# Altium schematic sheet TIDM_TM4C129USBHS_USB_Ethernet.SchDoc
size 431 x 279 mm; Date: Not shown in title block; ApprovedBy: Not shown in title block; CheckedBy: Not shown in title block; Author: Not shown in title block; CompanyName: Not shown in title block; Engineer: Not shown in title block; Organization: Not shown in title block; Address1: Not shown in title block; Address2: Not shown in title block; Address3: Not shown in title block; Address4: Not shown in title block; DocumentNumber: 1; Revision: Use project parameter SCH_Rev; SheetNumber: 3; SheetTotal: 3; PageSetup: Record=PageOptions¦CenterHorizontal=True¦CenterVertical=True¦PrintScale=1.00¦XCorrection=1.00¦YCorrection=1.00¦PrintKind=0¦BorderSize=5000000¦LeftOffset=0¦BottomOffset=0¦Orientation=2¦PaperLength=1000¦PaperWidth=1000¦Scale=100¦PaperSource=15¦PrintQuality=600¦MediaType=1¦DitherType=10¦PaperKind=Letter¦PrintScaleMode=1
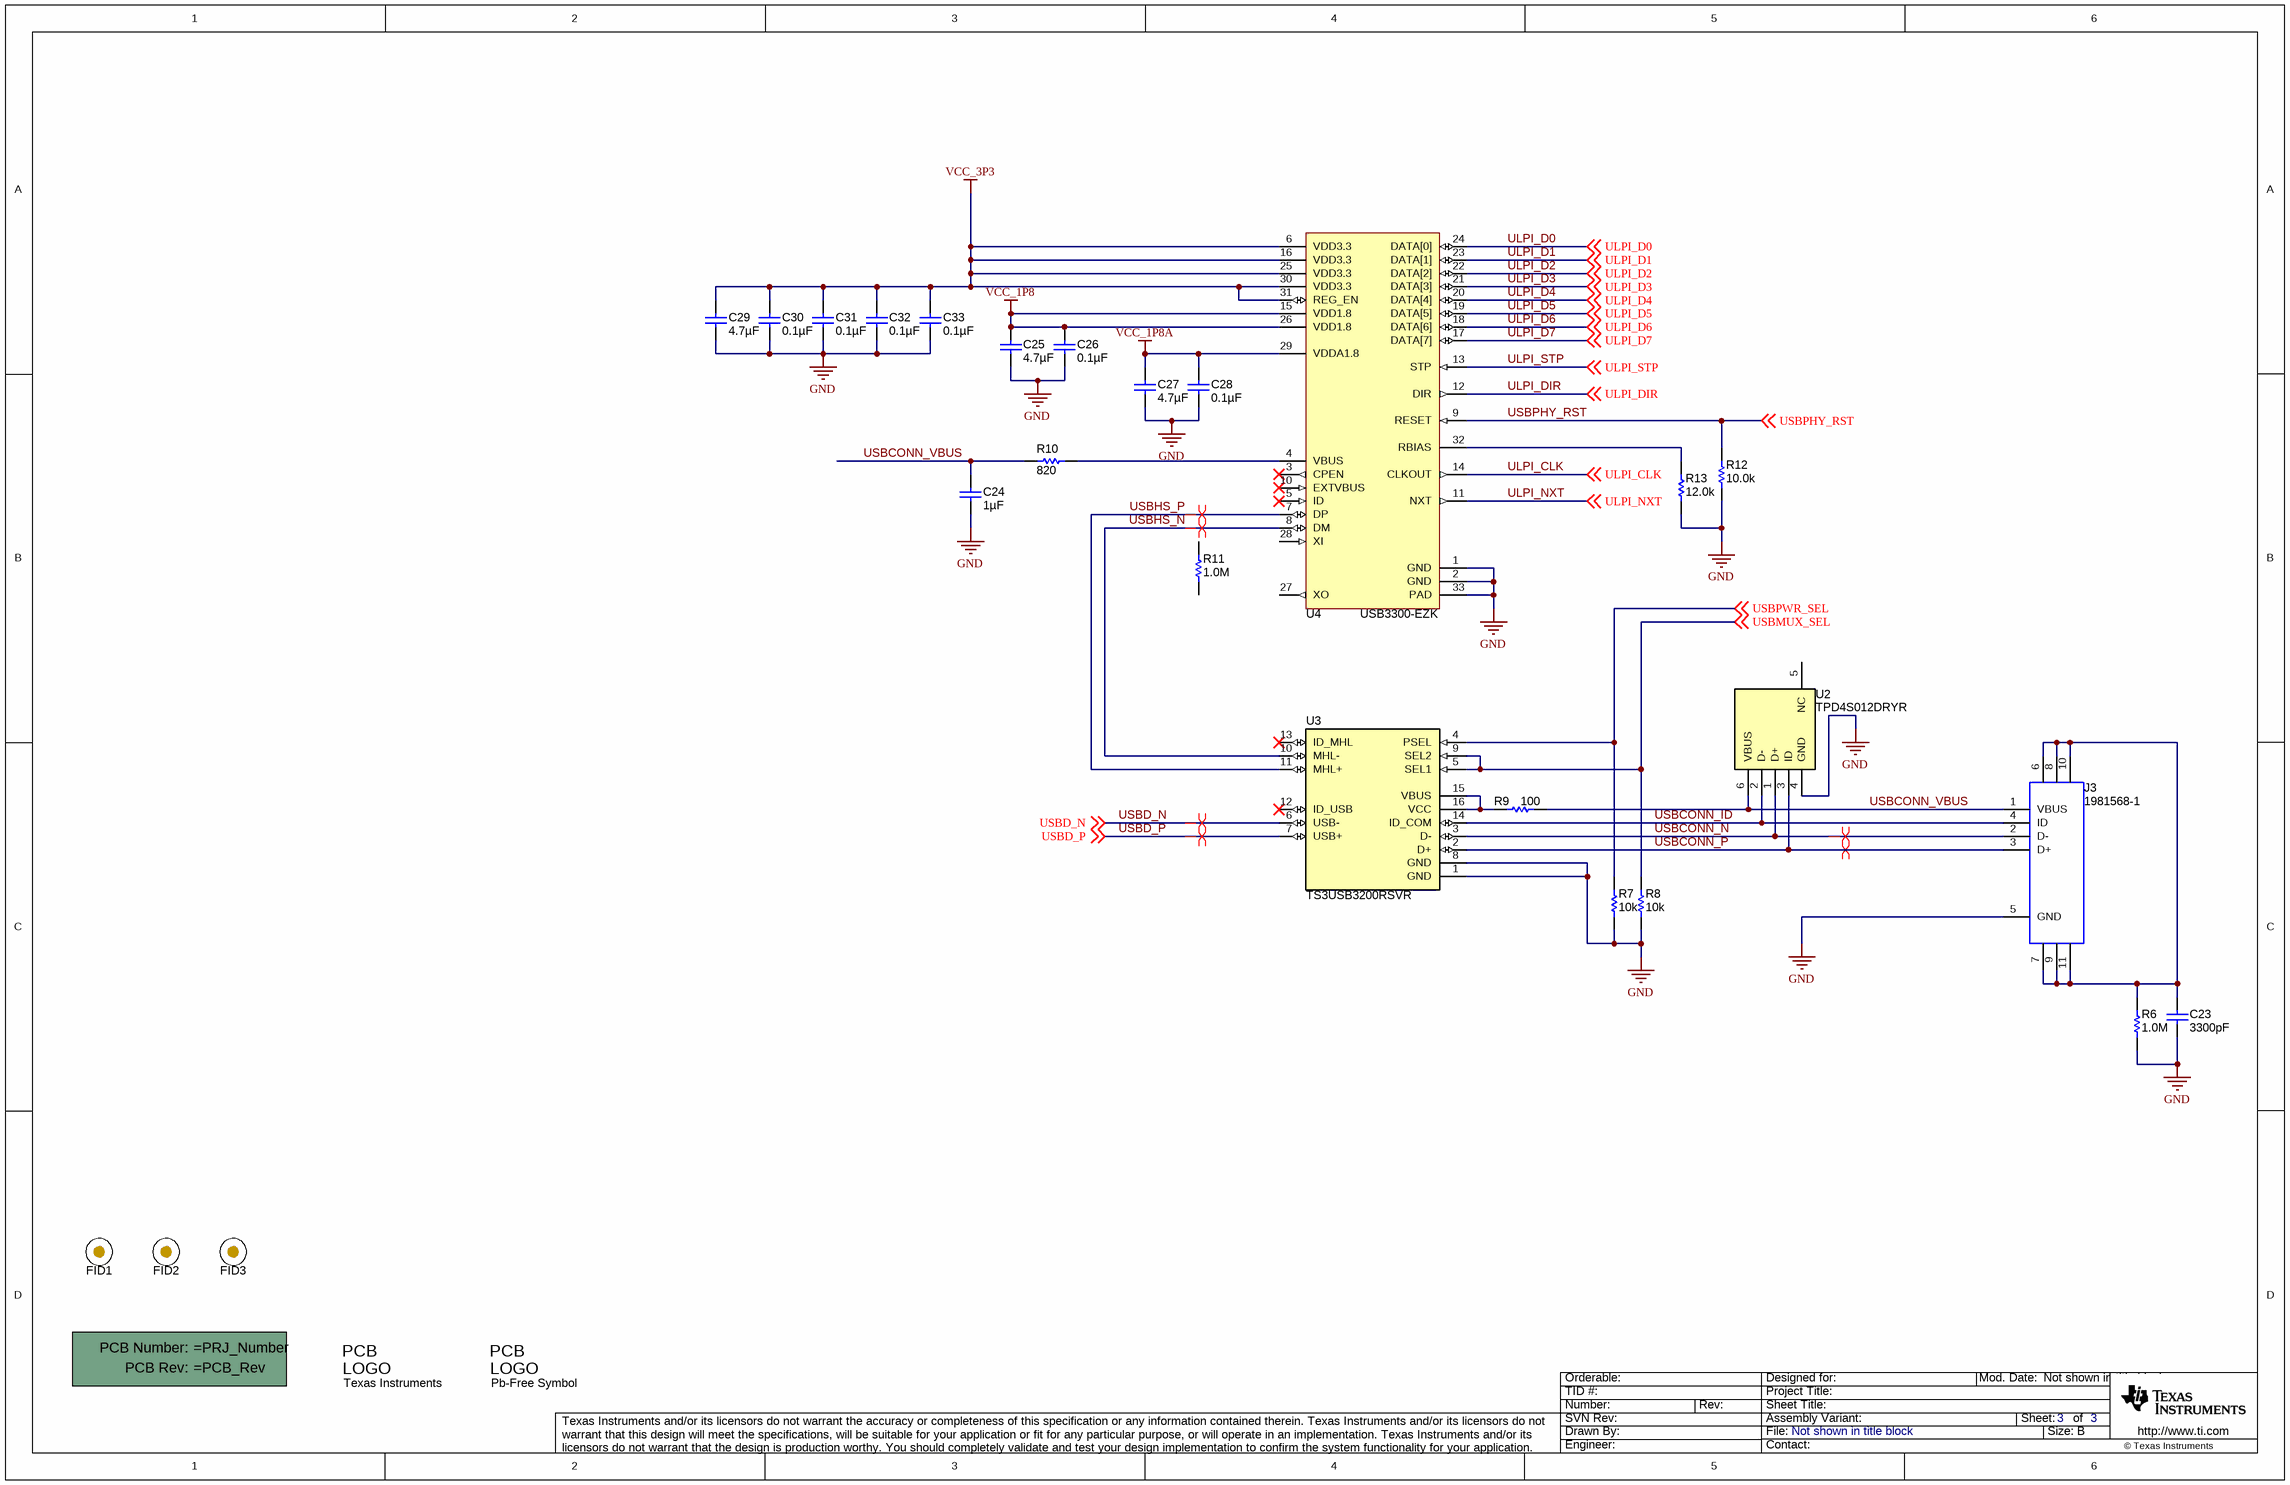
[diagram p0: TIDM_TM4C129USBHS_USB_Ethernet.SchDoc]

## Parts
!PCB  Printed Circuit Board  (value not drawn)  (mechanical)
C23  ValueDisplayed: 3300pF  [0603]  (hidden comment: C0603X332K5RACTU)
C24  ValueDisplayed: 1µF  [0603]  (hidden comment: GRM188R71A105KA61D)
C25  ValueDisplayed: 4.7µF  [0603]  (hidden comment: JMK107BB7475MA-T)
C26  ValueDisplayed: 0.1µF  [0603]  (hidden comment: 06035C104KAT2A)
C27  ValueDisplayed: 4.7µF  [0603]  (hidden comment: JMK107BB7475MA-T)
C28  ValueDisplayed: 0.1µF  [0603]  (hidden comment: 06035C104KAT2A)
C29  ValueDisplayed: 4.7µF  [0603]  (hidden comment: JMK107BB7475MA-T)
C30  ValueDisplayed: 0.1µF  [0603]  (hidden comment: 06035C104KAT2A)
C31  ValueDisplayed: 0.1µF  [0603]  (hidden comment: 06035C104KAT2A)
C32  ValueDisplayed: 0.1µF  [0603]  (hidden comment: 06035C104KAT2A)
C33  ValueDisplayed: 0.1µF  [0603]  (hidden comment: 06035C104KAT2A)
FID1  Fiducial  [Fiducial10-20]  (value not drawn)
FID2  Fiducial  [Fiducial10-20]  (value not drawn)
FID3  Fiducial  [Fiducial10-20]  (value not drawn)
J3  1981568-1  [TE_1981568-1]
Logo1  Texas Instruments  [TI_Stacked_Overlay_Small]  (no BOM)
Logo2  Pb-Free Symbol  [Pb-Free_Overlay_Small]  (no BOM)
R6  ValueDisplayed: 1.0M  [0603]  (hidden comment: CRCW06031M00JNEA)
R7  ValueDisplayed: 10k  [0603]  (hidden comment: RC0603JR-0710KL)
R8  ValueDisplayed: 10k  [0603]  (hidden comment: RC0603JR-0710KL)
R9  ValueDisplayed: 100  [0603]  (hidden comment: CRCW0603100RJNEA)
R10  ValueDisplayed: 820  [0603]  (hidden comment: RC0603FR-07820RL)
R11  ValueDisplayed: 1.0M  [0603]  (hidden comment: CRCW06031M00JNEA)
R12  ValueDisplayed: 10.0k  [0603]  (hidden comment: RCG060310K0FKEA)
R13  ValueDisplayed: 12.0k  [0603]  (hidden comment: RC0603FR-0712KL)
U2  TPD4S012DRYR  [DRY0006A]
U3  TS3USB3200RSVR  [RSV0016A]
U4  USB3300-EZK  [Microchip_32QFN-3304-5x5B]

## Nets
GND: C23.2 C24.2 C25.2 C26.2 C27.2 C28.2 C29.2 C30.2 C31.2 C32.2 C33.2 J3.5(GND) R6.1 R7.1 R8.1 R12.1 R13.1 U2.4(GND) U3.1(GND) U3.8(GND) U4.1(GND) U4.2(GND) U4.33(PAD)
VCC_1P8: C25.1 C26.1 U4.15(VDD1.8) U4.26(VDD1.8)
VCC_1P8A: C27.1 C28.1 U4.29(VDDA1.8)
VCC_3P3: C29.1 C30.1 C31.1 C32.1 C33.1 U4.6(VDD3.3) U4.16(VDD3.3) U4.25(VDD3.3) U4.30(VDD3.3) U4.31(REG_EN)
ULPI_CLK: U4.14(CLKOUT) ; off-sheet ULPI_CLK
ULPI_D0: U4.24(DATA[0]) ; off-sheet ULPI_D0
ULPI_D1: U4.23(DATA[1]) ; off-sheet ULPI_D1
ULPI_D2: U4.22(DATA[2]) ; off-sheet ULPI_D2
ULPI_D3: U4.21(DATA[3]) ; off-sheet ULPI_D3
ULPI_D4: U4.20(DATA[4]) ; off-sheet ULPI_D4
ULPI_D5: U4.19(DATA[5]) ; off-sheet ULPI_D5
ULPI_D6: U4.18(DATA[6]) ; off-sheet ULPI_D6
ULPI_D7: U4.17(DATA[7]) ; off-sheet ULPI_D7
ULPI_DIR: U4.12(DIR) ; off-sheet ULPI_DIR
ULPI_NXT: U4.11(NXT) ; off-sheet ULPI_NXT
ULPI_STP: U4.13(STP) ; off-sheet ULPI_STP
USBCONN_ID: J3.4(ID) U2.2(D-) U3.14(ID_COM)
USBCONN_N: J3.2(D-) U2.1(D+) U3.3(D-)
USBCONN_P: J3.3(D+) U2.3(ID) U3.2(D+)
USBCONN_VBUS: C24.1 J3.1(VBUS) R9.2 R10.1 U2.6(VBUS)
USBD_N: U3.6(USB-) ; off-sheet USBD_N
USBD_P: U3.7(USB+) ; off-sheet USBD_P
USBHS_N: U3.10(MHL-) U4.8(DM)
USBHS_P: U3.11(MHL+) U4.7(DP)
USBMUX_SEL: R8.2 U3.5(SEL1) U3.9(SEL2) ; off-sheet USBMUX_SEL
USBPHY_RST: R12.2 U4.9(RESET) ; off-sheet USBPHY_RST
USBPWR_SEL: R7.2 U3.4(PSEL) ; off-sheet USBPWR_SEL
NetC23_1: C23.1 J3.6 J3.7 J3.8 J3.9 J3.10 J3.11 R6.2
NetR9_1: R9.1 U3.15(VBUS) U3.16(VCC)
NetR10_2: R10.2 U4.4(VBUS)
NetR13_2: R13.2 U4.32(RBIAS)

Not connected (* = marked no-connect by the designer): R11 1 2; U2 5(NC); U3 12(ID_USB)* 13(ID_MHL)*; U4 3(CPEN)* 5(ID)* 10(EXTVBUS)* 27(XO) 28(XI)

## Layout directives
differential pair: USBCONN_N, USBCONN_P, USBD_N, USBD_P, USBHS_N, USBHS_P

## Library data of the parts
!PCB = PCB: Manufacturer: Any; SymbolCreator: a0412235
C23 = C0603X332K5RACTU: CAP, CERM, 3300 pF, 50 V, +/- 10%, X7R, 0603; Manufacturer: Kemet; Polarized: N; CompType: Capacitor; Value: 3300pF; U/M: EA; Cap_F: 0.0000000033; Tolerance_%: 10; Value1: Unknown; VDC_V: 50; Value2: 50V; TaMin_C: -55; TaMax_C: 125; AEC Category: Q200
C24 = GRM188R71A105KA61D: CAP, CERM, 1 µF, 10 V, +/- 10%, X7R, 0603; Manufacturer: MuRata; Polarized: N; CompType: Capacitor; Value: 1uF; U/M: EA; Cap_F: 0.000001; Tolerance_%: 10; ESR_ohm: 0.011; Value1: 0.011 ohm; Value2: 10V; TaMin_C: -55; TaMax_C: 125; AEC Category: Q200
C25 C27 C29 = JMK107BB7475MA-T: CAP, CERM, 4.7 µF, 6.3 V, +/- 10%, X7R, 0603; Manufacturer: Taiyo Yuden; Polarized: N; CompType: Capacitor; Value: 4.7uF; U/M: EA; Cap_F: 0.0000047; Tolerance_%: 10; Value1: Unknown; VDC_V: 6.3; Value2: 6.3V; TaMin_C: -55; TaMax_C: 125; AEC Category: Q200
C26 C28 C30-C33 = 06035C104KAT2A: CAP, CERM, 0.1 µF, 50 V, +/- 10%, X7R, 0603; Manufacturer: AVX; Polarized: N; CompType: Capacitor; Value: 0.1uF; U/M: EA; Cap_F: 0.0000001; Tolerance_%: 10; Value1: Unknown; VDC_V: 50; Value2: 50V; TaMin_C: -55; TaMax_C: 125; AEC Category: Q200
FID1-FID3 = Fiducial: Fiducial mark.  There is nothing to buy or mount.; SymbolCreator: codlsc
J3 = 1981568-1: Connector, Receptacle, Micro-USB Type B, R/A, Bottom Mount SMT; Manufacturer: TE Connectivity; SymbolCreator: a0411947
Logo1 = TI_Logo: Texas Instrument Corporate Signature; SymbolCreator: codlsc
Logo2 = Pb-Free: SymbolCreator: a0412235
R6 R11 = CRCW06031M00JNEA: RES, 1.0 M, 5%, 0.1 W, 0603; Manufacturer: Vishay-Dale; CompType: Resistor; Value: 1.0Meg; Res_ohm: 1000000; Value_Code: 1M00; Tolerance_%: 5; Power_W: 0.1; Value2: 0.1W; VDC_V: 75; TempCo: 200 ppm/C; EIA_Code: E24; U/M: EA; AEC Category: Q200
R7 R8 = RC0603JR-0710KL: RES, 10 k, 5%, 0.1 W, 0603; Manufacturer: Yageo America; CompType: Resistor; Value: 10k; Res_ohm: 10000; Value_Code: 10k0; Tolerance_%: 5; Power_W: 0.1; Value2: 0.1W; VDC_V: 50; TempCo: 100 ppm/C; EIA_Code: E24; U/M: EA; AEC Category: Q200
R9 = CRCW0603100RJNEA: RES, 100, 5%, 0.1 W, 0603; Manufacturer: Vishay-Dale; CompType: Resistor; Value: 100; Value_Code: 100R; Tolerance_%: 5; Power_W: 0.1; Value2: 0.1W; VDC_V: 75; TempCo: 200 ppm/C; EIA_Code: E24; U/M: EA; AEC Category: Q200
R10 = RC0603FR-07820RL: RES, 820, 1%, 0.1 W, 0603; Manufacturer: Yageo America; CompType: Resistor; Value: 820; Value_Code: 820R; Tolerance_%: 1; Power_W: 0.1; Value2: 0.1W; VDC_V: 150; TempCo: 200 ppm/C; U/M: EA; AEC Category: Q200
R12 = RCG060310K0FKEA: RES, 10.0 k, 1%, 0.1 W, 0603; Manufacturer: Vishay Draloric; CompType: Resistor; Value: 10.0k; Res_ohm: 10000; Value_Code: 10k0; Tolerance_%: 1; Power_W: 0.1; Value2: 0.1W; VDC_V: 75; TempCo: 100 ppm/C; EIA_Code: E96; U/M: EA; AEC Category: Q200; AEC Qualified: N
R13 = RC0603FR-0712KL: RES, 12.0 k, 1%, 0.1 W, 0603; Manufacturer: Yageo America; CompType: Resistor; Value: 12.0k; Res_ohm: 12000; Value_Code: 12k0; Tolerance_%: 1; Power_W: 0.1; Value2: 0.1W; VDC_V: 150; TempCo: 200 ppm/C; U/M: EA; AEC Category: Q200
U2 = TPD4S012DRYR: USB ESD Solution with Power Clamp, 4 Channels, -40 to +85 degC, 6-pin SON (DRY), Green (RoHS & no Sb/Br); Manufacturer: Texas Instruments; Alternate PartNumber: Equivalent; Breakdown Voltage(Min)(V): 6; IEC 61000-4-2 Air-Gap(+/- kV): 10; IO Capacitance(Typ)(pF): 0.8; USB High Speed: TRUE
U3 = TS3USB3200RSVR: DPDT USB 2.0 High-Speed (480Mbps) and Mobile High-Definition Link (MHL) Switch with ID Select and Flexible Power Control, RSV0016A; Manufacturer: Texas Instruments; SymbolCreator: a0411947; CompType: IC; U/M: EA
U4 = USB3300-EZK: Hi-Speed USB Host, Device or OTG PHY with ULPI Low Pin Interface, QFN-32; Manufacturer: Microchip; SymbolCreator: a0411947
